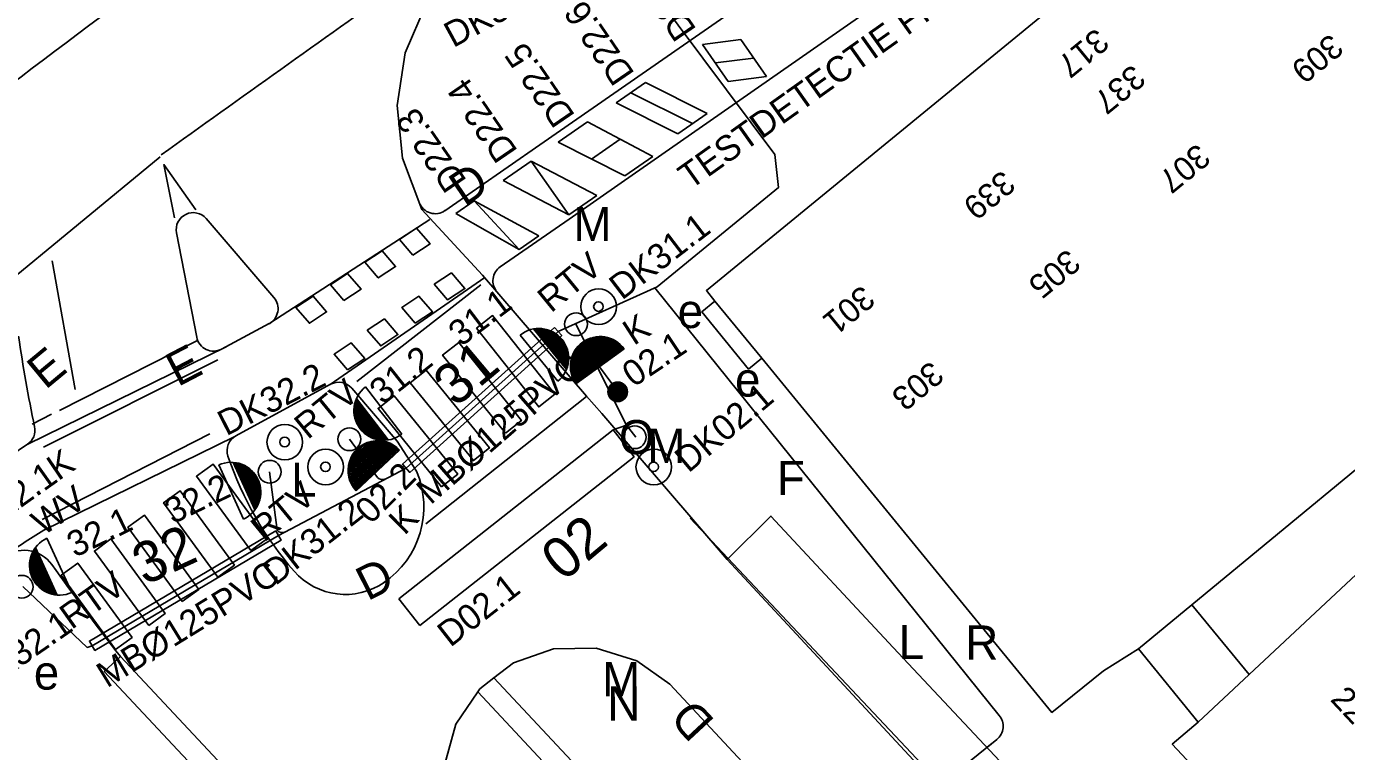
# Model space of a CAD drawing. Extents: x 81617 to 82144, y 454649 to 455150.
# Drawn here: x 81870.9 to 81909.62, y 454846.75 to 454868.02 of the extents above; entities that cross this region are included whole.
import ezdxf

# ---------------------------------------------------------------- set-up
doc = ezdxf.new("R2010")
doc.units = 0
for name, color, linetype in [('B-WE-OG-TOPOGRAFIE-G', 7, 'Continuous'), ('B-WE-VW-MARKERING-G', 7, 'Continuous'), ('N-OI-KL-VRI_KABEL_DETECTIE-G', 7, 'Continuous'), ('N-OI-KL-VRI_KABELGEUL-G', 7, 'Continuous'), ('N-OI-KL-VRI_LUS_DETECTIE-G', 7, 'Continuous'), ('N-OI-KL-VRI_LUS_DETECTIE-T18', 7, 'Continuous'), ('N-OI-KL-VRI_MANTELBUIS-G', 7, 'Continuous'), ('N-OI-KL-VRI_MANTELBUIS-T18', 7, 'Continuous'), ('N-WE-VW-VRI_ARMATUUR-S', 7, 'Continuous'), ('N-WE-VW-VRI_ARMATUUR-T18', 7, 'Continuous'), ('N-WE-VW-VRI_MAST-S', 7, 'Continuous'), ('N-WE-VW-VRI_RICHTINGNUMMER-T25', 7, 'Continuous')]:
    doc.layers.add(name, color=color, linetype=linetype)

msp = doc.modelspace()

# ---------------------------------------------------------------- linework, layer by layer
at = {"layer": 'B-WE-OG-TOPOGRAFIE-G'}
for p, q in [((81894.147, 454870.23), (81885.959, 454864.545)), ((81885.959, 454864.545), (81883.179, 454862.614)), ((81888.346, 454863.428), (81886.818, 454862.368)), ((81882.731, 454862.354), (81878.044, 454859.314)), ((81884.284, 454860.723), (81882.502, 454862.646)), ((81886.818, 454862.368), (81884.8, 454860.969)), ((81879.808, 454857.515), (81884.345, 454860.652)), ((81884.284, 454860.723), (81887.333, 454857.176)), ((81892.47, 454858.284), (81891.095, 454859.963)), ((81876.627, 454858.553), (81878.02, 454859.3)), ((81870.927, 454855.755), (81876.759, 454858.624)), ((81879.826, 454857.521), (81877.05, 454856.012)), ((81887.333, 454857.176), (81887.776, 454856.661)), ((81887.776, 454856.661), (81891.454, 454852.381)), ((81871.416, 454853.245), (81876.998, 454855.983)), ((81910.108, 454855.198), (81905.083, 454851.053)), ((81906.763, 454849.012), (81911.539, 454853.481)), ((81905.083, 454851.053), (81903.512, 454849.757)), ((81906.763, 454849.012), (81905.083, 454851.053)), ((81873.659, 454849.539), (81873.185, 454849.094)), ((81903.512, 454849.757), (81905.266, 454847.61)), ((81884.614, 454848.907), (81906.018, 454826.058)), ((81905.266, 454847.61), (81906.763, 454849.012)), ((81905.567, 454825.643), (81884.139, 454848.499))]:
    msp.add_line(p, q, dxfattribs=at)
for points in [[(81891.095, 454859.963), (81890.844, 454860.269), (81917.092, 454881.782)], [(81883.233, 454869.443), (81882.632, 454868.676), (81882.012, 454867.245), (81881.775, 454865.703), (81881.936, 454864.151), (81882.502, 454862.646)], [(81895.625, 454868.501), (81888.346, 454863.428)], [(81878.163, 454860.066), (81876.175, 454862.382)], [(81875.305, 454861.961), (81875.9, 454858.899)], [(81892.47, 454858.284), (81892.083, 454857.967), (81890.708, 454859.646), (81891.095, 454859.963)], [(81903.512, 454849.757), (81902.487, 454849.113), (81900.979, 454847.896), (81892.47, 454858.284)], [(81882.346, 454854.969), (81881.777, 454855.856), (81880.445, 454857.408)], [(81912.733, 454832.236), (81908.633, 454836.613), (81900.431, 454845.439), (81899.742, 454846.157), (81896.321, 454849.804), (81892.737, 454853.657), (81891.454, 454852.381)], [(81891.454, 454852.381), (81907.325, 454835.276), (81911.365, 454830.977)], [(81876.51, 454846.498), (81873.659, 454849.539)], [(81908.659, 454828.488), (81900.257, 454837.458), (81889.774, 454848.723), (81888.801, 454849.41), (81887.61, 454849.782), (81886.363, 454849.76), (81885.185, 454849.348), (81884.614, 454848.907)], [(81876.027, 454846.063), (81875.486, 454846.64), (81873.185, 454849.094)], [(81884.614, 454848.907), (81884.198, 454848.585), (81884.139, 454848.499)], [(81884.139, 454848.499), (81883.499, 454847.551), (81883.162, 454846.35), (81883.219, 454845.104), (81883.666, 454843.939), (81884.456, 454842.973), (81886.737, 454840.646), (81887.397, 454839.898), (81903.018, 454823.298)], [(81915.707, 454834.971), (81906.614, 454844.709), (81904.504, 454846.96), (81905.266, 454847.61)]]:
    msp.add_lwpolyline(points, dxfattribs=at)
for centre, radius, start, end in [((81882.894, 454863.025), 0.5, 200.6076, 304.7727), ((81875.796, 454862.056), 0.5, 40.6422, 190.9986), ((81885.085, 454860.558), 0.5, 124.7359, 220.6823), ((81877.784, 454859.74), 0.5, 298.1915, 40.6422), ((81909.402, 454864.455), 39.12, 188.1206, 192.063), ((81876.391, 454858.994), 0.5, 190.9986, 298.1915), ((81880.065, 454857.082), 0.5, 40.6622, 118.5313), ((81870.656, 454856.175), 0.5, 302.7903, 12.063), ((81883.766, 454835.824), 23.708, 122.7903, 130.5415), ((81877.288, 454855.572), 0.5, 118.5313, 198.674), ((81886.288, 454858.614), 10, 198.674, 221.0999), ((81879.867, 454853.923), 2.691, 304.196, 22.8684), ((81878.198, 454841.916), 13.204, 120.9031, 127.375), ((81870.835, 454851.651), 1, 35.4028, 130.7582), ((81930.678, 454894.184), 72.418, 215.40281, 218.06073), ((81880.26, 454853.355), 2, 221.0999, 304.6801)]:
    msp.add_arc(centre, radius, start, end, dxfattribs=at)
at = {"layer": 'B-WE-VW-MARKERING-G'}
for p, q in [((81869.8, 454860.056), (81874.825, 454864.194)), ((81871.663, 454861.142), (81872.333, 454857.367)), ((81887.331, 454857.162), (81882.614, 454853.424)), ((81890.366, 454853.591), (81900.01, 454843.365))]:
    msp.add_line(p, q, dxfattribs=at)
for points in [[(81875.249, 454862.4), (81874.937, 454863.965), (81875.873, 454862.642)], [(81880.598, 454857.599), (81884.227, 454860.434)], [(81875.919, 454858.802), (81871.872, 454856.757)], [(81871.402, 454855.675), (81876.516, 454858.234)], [(81871.644, 454856.649), (81871.071, 454856.356)], [(81871.364, 454853.551), (81876.283, 454856.072)]]:
    msp.add_lwpolyline(points, dxfattribs=at)
for points in [[(81882.235, 454861.308), (81881.841, 454861.767), (81882.346, 454862.099), (81882.74, 454861.641)], [(81880.83, 454861.102), (81881.224, 454860.643), (81881.73, 454860.976), (81881.336, 454861.434)], [(81880.214, 454859.978), (81879.82, 454860.437), (81880.325, 454860.769), (81880.719, 454860.31)], [(81882.862, 454860.455), (81883.256, 454859.996), (81883.762, 454860.329), (81883.367, 454860.788)], [(81878.809, 454859.772), (81879.203, 454859.313), (81879.708, 454859.645), (81879.314, 454860.104)], [(81882.303, 454859.311), (81881.909, 454859.769), (81882.414, 454860.102), (81882.808, 454859.643)], [(81880.899, 454859.105), (81881.293, 454858.646), (81881.798, 454858.979), (81881.404, 454859.437)], [(81884.104, 454859.164), (81885.93, 454856.856), (81886.402, 454857.227), (81884.576, 454859.535)], [(81880.319, 454857.943), (81879.925, 454858.402), (81880.431, 454858.735), (81880.825, 454858.276)], [(81884.949, 454856.083), (81883.109, 454858.38), (81883.581, 454858.751), (81885.421, 454856.455)], [(81882.155, 454857.564), (81884.013, 454855.282), (81884.484, 454855.654), (81882.627, 454857.935)], [(81883.08, 454854.513), (81881.217, 454856.814), (81881.688, 454857.186), (81883.552, 454854.885)], [(81877.485, 454852.643), (81875.892, 454854.824), (81876.377, 454855.178), (81877.97, 454852.997)], [(81876.521, 454851.865), (81874.928, 454854.045), (81875.413, 454854.399), (81877.006, 454852.219)], [(81875.473, 454851.147), (81873.88, 454853.328), (81874.365, 454853.682), (81875.958, 454851.501)], [(81874.491, 454850.448), (81872.898, 454852.629), (81873.383, 454852.983), (81874.976, 454850.802)], [(81873.517, 454849.74), (81871.924, 454851.92), (81872.409, 454852.274), (81874.002, 454850.094)]]:
    msp.add_lwpolyline(points, close=True, dxfattribs=at)
for centre, radius, start, end in [((81999.362, 454697.85), 212.13, 125.19968, 128.77534), ((82436.117, 454084.333), 960.875, 125.226465, 125.740356)]:
    msp.add_arc(centre, radius, start, end, dxfattribs=at)
at = {"layer": 'N-OI-KL-VRI_KABEL_DETECTIE-G'}
for p, q in [((81888.112, 454856.182), (81888.506, 454856.324)), ((81896.703, 454844.959), (81899.228, 454846.997))]:
    msp.add_line(p, q, dxfattribs=at)
at = {"layer": 'N-OI-KL-VRI_KABELGEUL-G'}
for p, q in [((81881.2, 454854.791), (81880.376, 454855.91)), ((81878.037, 454854.954), (81878.256, 454853.238))]:
    msp.add_line(p, q, dxfattribs=at)
for points in [[(81886.495, 454859.072), (81889.398, 454860.377), (81892.955, 454863.292), (81892.853, 454864.259), (81887.904, 454870.888), (81877.049, 454882.767)], [(81889.329, 454860.346), (81899.434, 454847.81)], [(81887.01, 454859.303), (81888.506, 454856.324), (81888.78, 454855.972)], [(81870.802, 454851.587), (81872.685, 454849.803), (81872.834, 454849.851), (81878.298, 454853.089), (81882.037, 454855.056), (81886.495, 454859.072)], [(81899.361, 454847.104), (81899.095, 454846.89)]]:
    msp.add_lwpolyline(points, dxfattribs=at)
for centre, radius, start, end in [((81881.352, 454854.921), 0.2, 220.6622, 298.9699), ((81878.406, 454853.371), 0.2, 221.7221, 298.726), ((81899.047, 454847.493), 0.5, 308.9045, 39.3217)]:
    msp.add_arc(centre, radius, start, end, dxfattribs=at)
at = {"layer": 'N-OI-KL-VRI_LUS_DETECTIE-G'}
for p, q in [((81891.85, 454867.634), (81890.733, 454867.491)), ((81891.485, 454866.407), (81890.733, 454867.491)), ((81892.603, 454866.551), (81891.85, 454867.634)), ((81892.226, 454867.092), (81891.109, 454866.949)), ((81889.059, 454866.372), (81888.196, 454865.773)), ((81889.059, 454866.372), (81890.869, 454865.468)), ((81892.603, 454866.551), (81891.485, 454866.407)), ((81888.627, 454866.073), (81890.437, 454865.169)), ((81888.196, 454865.773), (81890.006, 454864.87)), ((81890.869, 454865.468), (81890.006, 454864.87)), ((81887.356, 454865.22), (81886.494, 454864.621)), ((81889.277, 454864.207), (81887.356, 454865.22)), ((81888.317, 454864.713), (81887.475, 454864.129)), ((81886.494, 454864.621), (81888.456, 454863.636)), ((81885.707, 454864.071), (81884.886, 454863.501)), ((81887.628, 454863.058), (81885.707, 454864.071)), ((81886.807, 454862.488), (81885.707, 454864.071)), ((81888.456, 454863.636), (81889.277, 454864.207)), ((81884.886, 454863.501), (81886.807, 454862.488)), ((81884.035, 454862.904), (81883.496, 454862.53)), ((81885.931, 454861.875), (81884.035, 454862.904)), ((81885.355, 454861.476), (81884.035, 454862.904)), ((81886.807, 454862.488), (81887.628, 454863.058)), ((81883.496, 454862.53), (81885.355, 454861.476)), ((81885.355, 454861.476), (81885.931, 454861.875)), ((81885.343, 454861.485), (81885.372, 454861.487)), ((81885.343, 454861.485), (81885.372, 454861.487)), ((81888.112, 454856.182), (81881.828, 454851.232)), ((81888.731, 454855.396), (81888.112, 454856.182)), ((81882.446, 454850.446), (81888.731, 454855.396)), ((81881.828, 454851.232), (81882.446, 454850.446))]:
    msp.add_line(p, q, dxfattribs=at)
at = {"layer": 'N-OI-KL-VRI_MANTELBUIS-G'}
for points in [[(81886.388, 454859.19), (81886.602, 454858.953), (81882.144, 454854.937), (81881.93, 454855.175), (81886.388, 454859.19)], [(81878.216, 454853.226), (81878.379, 454852.951), (81872.915, 454849.713), (81872.752, 454849.989), (81878.216, 454853.226)]]:
    msp.add_lwpolyline(points, dxfattribs=at)
at = {"layer": 'N-WE-VW-VRI_ARMATUUR-S'}
for p, q in [((81885.381, 454858.963), (81886.487, 454857.608)), ((81885.775, 454859.144), (81886.742, 454857.958)), ((81885.809, 454859.15), (81886.755, 454857.989)), ((81885.844, 454859.155), (81886.767, 454858.022)), ((81885.882, 454859.157), (81886.777, 454858.058)), ((81885.919, 454859.16), (81886.785, 454858.095)), ((81885.958, 454859.159), (81886.793, 454858.133)), ((81885.998, 454859.156), (81886.8, 454858.173)), ((81886.04, 454859.152), (81886.807, 454858.216)), ((81886.085, 454859.146), (81886.807, 454858.26)), ((81886.132, 454859.138), (81886.806, 454858.308)), ((81886.18, 454859.123), (81886.803, 454858.358)), ((81886.233, 454859.107), (81886.798, 454858.414)), ((81886.292, 454859.082), (81886.788, 454858.477)), ((81886.357, 454859.05), (81886.767, 454858.547)), ((81886.437, 454858.999), (81886.734, 454858.634)), ((81886.568, 454858.886), (81886.652, 454858.786)), ((81886.855, 454858.084), (81887.969, 454858.886)), ((81886.855, 454858.047), (81888.006, 454858.876)), ((81886.855, 454858.01), (81888.039, 454858.863)), ((81886.857, 454858.122), (81887.929, 454858.897)), ((81886.858, 454857.975), (81888.073, 454858.85)), ((81886.862, 454857.939), (81888.102, 454858.837)), ((81886.863, 454858.163), (81887.891, 454858.906)), ((81886.868, 454857.905), (81888.132, 454858.821)), ((81886.871, 454858.204), (81887.849, 454858.913)), ((81886.879, 454858.249), (81887.804, 454858.917)), ((81886.89, 454858.294), (81887.756, 454858.921)), ((81886.906, 454858.34), (81887.708, 454858.92)), ((81886.926, 454858.394), (81887.65, 454858.918)), ((81886.953, 454858.45), (81887.589, 454858.91)), ((81886.99, 454858.512), (81887.515, 454858.894)), ((81887.044, 454858.59), (81887.427, 454858.867)), ((81886.873, 454857.875), (81888.163, 454858.803)), ((81886.879, 454857.84), (81888.192, 454858.788)), ((81886.885, 454857.811), (81888.216, 454858.771)), ((81886.897, 454857.779), (81888.243, 454858.753)), ((81886.906, 454857.751), (81888.269, 454858.733)), ((81886.918, 454857.722), (81888.29, 454858.715)), ((81886.931, 454857.692), (81888.315, 454858.694)), ((81886.942, 454857.666), (81888.338, 454858.674)), ((81886.958, 454857.638), (81888.357, 454858.652)), ((81886.973, 454857.611), (81888.378, 454858.629)), ((81886.985, 454857.586), (81888.4, 454858.608)), ((81887.003, 454857.561), (81888.418, 454858.582)), ((81887.019, 454857.536), (81888.437, 454858.558)), ((81887.168, 454858.714), (81887.271, 454858.792)), ((81888.071, 454857.541), (81887.71, 454858.032)), ((81881.915, 454856.058), (81880.848, 454857.443)), ((81881.293, 454855.882), (81880.518, 454856.887)), ((81881.333, 454855.879), (81880.527, 454856.928)), ((81881.372, 454855.876), (81880.536, 454856.965)), ((81881.409, 454855.878), (81880.545, 454857.002)), ((81881.447, 454855.879), (81880.556, 454857.037)), ((81881.482, 454855.883), (81880.569, 454857.07)), ((81881.516, 454855.888), (81880.583, 454857.101)), ((81881.206, 454855.895), (81880.509, 454856.801)), ((81881.159, 454855.904), (81880.509, 454856.752)), ((81881.112, 454855.921), (81880.51, 454856.703)), ((81881.251, 454855.888), (81880.511, 454856.845)), ((81881.059, 454855.938), (81880.514, 454856.647)), ((81881.002, 454855.964), (81880.522, 454856.584)), ((81880.937, 454855.998), (81880.542, 454856.513)), ((81880.859, 454856.052), (81880.572, 454856.425)), ((81880.731, 454856.169), (81880.65, 454856.271)), ((81880.335, 454855.001), (81881.263, 454855.867)), ((81880.336, 454854.961), (81881.304, 454855.863)), ((81880.338, 454855.044), (81881.22, 454855.87)), ((81880.339, 454854.922), (81881.342, 454855.858)), ((81880.341, 454855.088), (81881.176, 454855.867)), ((81880.343, 454854.885), (81881.38, 454855.852)), ((81880.346, 454855.137), (81881.127, 454855.865)), ((81880.348, 454854.848), (81881.415, 454855.844)), ((81880.354, 454854.814), (81881.45, 454855.835)), ((81880.357, 454855.185), (81881.079, 454855.859)), ((81880.362, 454854.78), (81881.481, 454855.824)), ((81880.37, 454855.241), (81881.022, 454855.85)), ((81880.373, 454854.747), (81881.514, 454855.813)), ((81880.381, 454854.716), (81881.546, 454855.801)), ((81880.39, 454855.298), (81880.962, 454855.834)), ((81880.392, 454854.685), (81881.575, 454855.788)), ((81880.403, 454854.656), (81881.603, 454855.776)), ((81880.418, 454855.365), (81880.891, 454855.809)), ((81880.418, 454854.627), (81881.63, 454855.76)), ((81880.43, 454854.6), (81881.659, 454855.743)), ((81880.446, 454854.571), (81881.684, 454855.728)), ((81880.464, 454855.449), (81880.807, 454855.772)), ((81880.462, 454854.545), (81881.709, 454855.711)), ((81880.476, 454854.52), (81881.736, 454855.692)), ((81880.495, 454854.493), (81881.758, 454855.675)), ((81880.513, 454854.469), (81881.781, 454855.655)), ((81880.53, 454854.444), (81881.804, 454855.635)), ((81880.551, 454854.423), (81881.826, 454855.612)), ((81880.569, 454855.588), (81880.662, 454855.677)), ((81880.57, 454854.399), (81881.848, 454855.592)), ((81876.544, 454855.156), (81877.27, 454853.564)), ((81876.972, 454855.23), (81877.606, 454853.838)), ((81877.006, 454855.227), (81877.626, 454853.865)), ((81877.041, 454855.223), (81877.646, 454853.894)), ((81877.078, 454855.216), (81877.665, 454853.925)), ((81877.114, 454855.21), (81877.682, 454853.96)), ((81877.152, 454855.198), (81877.7, 454853.994)), ((81877.19, 454855.186), (81877.717, 454854.031)), ((81877.23, 454855.171), (81877.734, 454854.071)), ((81877.271, 454855.154), (81877.745, 454854.113)), ((81877.315, 454855.134), (81877.757, 454854.161)), ((81877.357, 454855.107), (81877.766, 454854.209)), ((81877.405, 454855.078), (81877.775, 454854.265)), ((81877.455, 454855.04), (81877.782, 454854.328)), ((81877.51, 454854.992), (81877.779, 454854.401)), ((81877.574, 454854.923), (81877.77, 454854.494)), ((81877.673, 454854.779), (81877.728, 454854.662)), ((81871.701, 454851.354), (81871.112, 454852.643)), ((81871.738, 454851.347), (81871.13, 454852.675)), ((81871.773, 454851.343), (81871.15, 454852.704)), ((81871.807, 454851.34), (81871.171, 454852.731)), ((81872.235, 454851.415), (81871.506, 454853.005)), ((81871.324, 454851.53), (81870.996, 454852.241)), ((81871.374, 454851.491), (81871.002, 454852.304)), ((81871.421, 454851.462), (81871.011, 454852.36)), ((81871.464, 454851.435), (81871.021, 454852.408)), ((81871.508, 454851.416), (81871.032, 454852.455)), ((81871.549, 454851.399), (81871.043, 454852.498)), ((81871.589, 454851.384), (81871.06, 454852.537)), ((81871.627, 454851.371), (81871.077, 454852.575)), ((81871.665, 454851.36), (81871.095, 454852.609)), ((81871.269, 454851.577), (81870.999, 454852.167)), ((81871.204, 454851.646), (81871.008, 454852.075)), ((81871.106, 454851.789), (81871.05, 454851.907))]:
    msp.add_line(p, q, dxfattribs=at)
for centre, radius in [((81887.684, 454859.797), 0.522), ((81887.679, 454859.801), 0.141), ((81888.244, 454857.299), 0.286), ((81888.244, 454857.299), 0.256), ((81888.244, 454857.299), 0.226), ((81888.244, 454857.299), 0.196), ((81888.244, 454857.299), 0.166), ((81888.244, 454857.299), 0.136), ((81888.244, 454857.299), 0.106), ((81888.244, 454857.299), 0.0765), ((81888.244, 454857.299), 0.0465), ((81888.244, 454857.299), 0.0165), ((81878.481, 454855.824), 0.522), ((81878.476, 454855.828), 0.141), ((81879.68, 454855.096), 0.522), ((81889.302, 454855.096), 0.522), ((81879.674, 454855.1), 0.141), ((81889.296, 454855.1), 0.141)]:
    msp.add_circle(centre, radius, dxfattribs=at)
for centre, start, end in [((81885.934, 454858.286), 309.1845, 129.1845), ((81887.728, 454858.047), 35.8439, 215.8439), ((81881.381, 454856.751), 127.5822, 307.5822), ((81881.209, 454854.995), 43.0061, 223.0061), ((81876.907, 454854.36), 294.4799, 114.4799), ((81871.87, 454852.21), 114.5883, 294.5883)]:
    msp.add_arc(centre, 0.873, start, end, dxfattribs=at)
at = {"layer": 'N-WE-VW-VRI_MAST-S'}
for centre in [(81887.022, 454859.284), (81880.376, 454855.91), (81888.743, 454855.969), (81878.037, 454854.954), (81870.767, 454851.581)]:
    msp.add_circle(centre, 0.335, dxfattribs=at)

# ---------------------------------------------------------------- texts
at = {"layer": 'B-WE-OG-TOPOGRAFIE-G'}
for s, height, rotation, p in [('317', 0.7, 219.3913, (81902.277, 454867.998)), ('309', 0.7, 219.3386, (81909.147, 454867.836)), ('337', 0.7, 219.3913, (81903.346, 454866.934)), ('307', 0.7, 219.3913, (81905.248, 454864.614)), ('D', 1, 33.854, (81883.749, 454862.716)), ('339', 0.7, 219.3386, (81899.528, 454863.831)), ('305', 0.7, 219.3386, (81901.439, 454861.519)), ('301', 0.7, 219.3386, (81895.412, 454860.458)), ('E', 1, 39.6415, (81871.462, 454857.344)), ('E', 1, 27.564, (81875.346, 454857.435)), ('303', 0.7, 219.3386, (81897.431, 454858.234)), ('D', 1, 26.8135, (81880.909, 454851.15)), ('22', 0.7, 313.0822, (81909.116, 454848.257)), ('D', 1, 132.9071, (81891.123, 454847.647))]:
    msp.add_text(s, height=height, rotation=rotation, dxfattribs=at).set_placement(p)
for s, p in [('M', (81886.949, 454861.723)), ('e', (81890.004, 454859.171)), ('e', (81891.685, 454857.161)), ('O', (81888.28, 454855.472)), ('M', (81889.114, 454855.217)), ('L', (81878.667, 454854.221)), ('F', (81892.915, 454854.27)), ('L', (81896.484, 454849.462)), ('R', (81898.438, 454849.447)), ('e', (81871.122, 454848.565)), ('M', (81887.789, 454848.372)), ('N', (81887.94, 454847.658))]:
    msp.add_text(s, height=1, dxfattribs=at).set_placement(p)
at = {"layer": 'N-OI-KL-VRI_LUS_DETECTIE-T18'}
for s, rotation, p in [('D22.7', 124.4022, (81890.572, 454867.928)), ('TESTDETECTIE FIETS', 35.3937, (81890.371, 454863.214)), ('D22.6', 124.4022, (81888.76, 454866.634)), ('D22.5', 124.4022, (81887.014, 454865.402)), ('D22.4', 124.4022, (81885.331, 454864.364)), ('D22.3', 124.6479, (81883.836, 454863.493)), ('D02.1', 38.0326, (81883.336, 454849.787))]:
    msp.add_text(s, height=0.75, rotation=rotation, dxfattribs=at).set_placement(p)
at = {"layer": 'N-OI-KL-VRI_MANTELBUIS-T18'}
for rotation, p in [(41.0673, (81882.756, 454853.966)), (31.5921, (81873.267, 454848.599))]:
    msp.add_text('MB%%C125PVC', height=0.75, rotation=rotation, dxfattribs=at).set_placement(p)
at = {"layer": 'N-WE-VW-VRI_ARMATUUR-S'}
for s, rotation, p in [('RTV', 39.3238, (81886.289, 454859.597)), ('K', 32.9093, (81888.715, 454858.642)), ('RTV', 39.3238, (81879.155, 454855.881)), ('K', 34.0253, (81871.837, 454854.674)), ('WV', 34.9007, (81871.398, 454853.059)), ('RTV', 39.3238, (81877.88, 454852.87)), ('K', 44.5483, (81881.987, 454853.071)), ('RTV', 35.2878, (81872.228, 454850.31))]:
    msp.add_text(s, height=0.75, rotation=rotation, dxfattribs=at).set_placement(p)
at = {"layer": 'N-WE-VW-VRI_ARMATUUR-T18'}
for s, rotation, p in [('DK39.1', 28.5657, (81883.422, 454867.381)), ('DK31.1', 37.4045, (81888.367, 454859.97)), ('31.1', 37.1696, (81883.648, 454858.604)), ('02.1', 33.7392, (81888.704, 454857.414)), ('31.2', 38.4613, (81881.351, 454856.902)), ('DK32.2', 27.0734, (81876.765, 454855.99)), ('DK02.1', 40.0117, (81890.318, 454854.9)), ('22.1', 35.3763, (81870.277, 454853.558)), ('02.2', 44.8762, (81881, 454853.388)), ('32.2', 25.6188, (81875.196, 454853.409)), ('32.1', 25.8823, (81872.327, 454852.427)), ('DK31.2', 38.01, (81878.206, 454851.597)), ('DK32.1', 34.6846, (81869.567, 454848.415))]:
    msp.add_text(s, height=0.75, rotation=rotation, dxfattribs=at).set_placement(p)
at = {"layer": 'N-WE-VW-VRI_RICHTINGNUMMER-T25'}
for s, rotation, p in [('31', 40, (81883.489, 454856.824)), ('02', 40, (81886.652, 454851.709)), ('32', 24.5942, (81874.374, 454851.613))]:
    msp.add_text(s, height=1.2, rotation=rotation, dxfattribs=at).set_placement(p)

doc.saveas('drawing.dxf')
